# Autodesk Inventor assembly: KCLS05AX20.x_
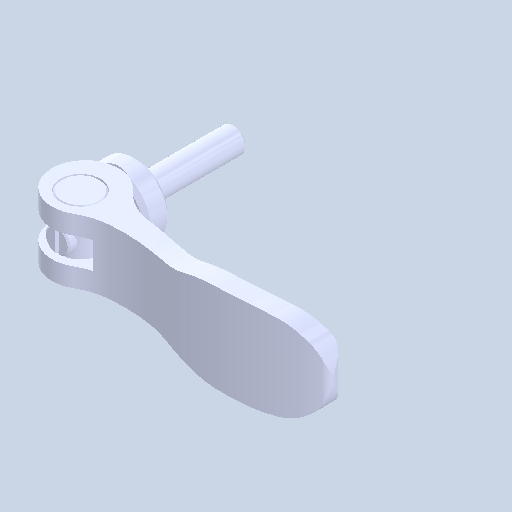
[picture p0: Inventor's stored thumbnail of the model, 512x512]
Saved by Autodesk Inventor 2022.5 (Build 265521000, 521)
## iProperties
Created: 2024-08
Part Number: KCLS05AX20.x_
Document SubType Name: Assembly
Designer: ImaoCorp
Author: ImaoCorp
Sending System: SOLIDWORKS 2022-2022290
MC: AMD64
MC_MODEL: Intel64 Family 6 Model 60 Stepping 3, GenuineIntel
OS: Windows_NT
FRU: Parasolid Version 33.1, build 260,  4-25-2022
FORMAT: text
GUISE: transmit
KEY: FILEKCLS05AX20.x_t
DATE: Thu Aug 29 10:54:27 2024
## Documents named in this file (5)
- Y:\5.更新分\2024年対応\1001_KCL\データ\kcls05ax20\KCLS05AX20.x_.iam
- Y:\5.更新分\2024年対応\1001_KCL\データ\kcls05ax20\KCLS05AX20_01.ipt
- Y:\5.更新分\2024年対応\1001_KCL\データ\kcls05ax20\KCLS05AX20_02.ipt
- Y:\5.更新分\2024年対応\1001_KCL\データ\kcls05ax20\KCLS05AX20_03.ipt
- Y:\5.更新分\2024年対応\1001_KCL\データ\kcls05ax20\KCLS05AX20_04.ipt
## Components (4 placed, 4 different names)
1. KCLS05AX20_01
2. KCLS05AX20_02
3. KCLS05AX20_03
4. KCLS05AX20_04
